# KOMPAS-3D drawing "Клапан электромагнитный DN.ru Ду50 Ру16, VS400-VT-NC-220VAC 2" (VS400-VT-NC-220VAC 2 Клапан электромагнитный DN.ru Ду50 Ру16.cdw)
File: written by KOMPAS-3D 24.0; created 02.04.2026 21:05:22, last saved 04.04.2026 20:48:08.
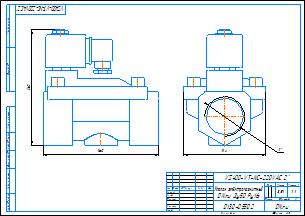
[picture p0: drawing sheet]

Document properties: c3d_UniqueCompID: ef56311e-7521-43dc-8291-0e6108b3d81d; Обозначение: VS400-ET-NC-220VAC 2; Наименование: Клапан электромагнитный DN.ru Ду50 Ру16; Автор: artio; Класс точности: c; Знак неуказанной шероховатости: Шероховатость не задана; Рассекать на разрезах: Да; c3d_UniqueCompID: ef56311e-7521-43dc-8291-0e6108b3d81d; Обозначение: VS400-ET-NC-220VAC 1; Наименование: Клапан электромагнитный DN.ru Ду25 Ру16; Автор: artio; Класс точности: c; Знак неуказанной шероховатости: Шероховатость не задана; Рассекать на разрезах: Да; c3d_UniqueCompID: ef56311e-7521-43dc-8291-0e6108b3d81d; Обозначение: VS400-ET-NC-220VAC 1-2; Наименование: Клапан электромагнитный DN.ru Ду15 Ру16; Автор: artio; Класс точности: c; Знак неуказанной шероховатости: Шероховатость не задана; Рассекать на разрезах: Да; c3d_UniqueCompID: ef56311e-7521-43dc-8291-0e6108b3d81d; Обозначение: VS400-ET-NC-220VAC 3-4; Наименование: Клапан электромагнитный DN.ru Ду20 Ру16; Автор: artio; Класс точности: c; Знак неуказанной шероховатости: Шероховатость не задана; Рассекать на разрезах: Да; c3d_UniqueCompID: ef56311e-7521-43dc-8291-0e6108b3d81d; Обозначение: VS400-ET-NC-220VAC 1 1-4; Наименование: Клапан электромагнитный DN.ru Ду32 Ру16; Автор: artio; Класс точности: c; Знак неуказанной шероховатости: Шероховатость не задана; Рассекать на разрезах: Да; c3d_UniqueCompID: ef56311e-7521-43dc-8291-0e6108b3d81d; Обозначение: VS400-ET-NC-220VAC 3-8; Наименование: Клапан электромагнитный DN.ru Ду10 Ру16; Автор: artio; Класс точности: c; Знак неуказанной шероховатости: Шероховатость не задана; Рассекать на разрезах: Да; c3d_UniqueCompID: ef56311e-7521-43dc-8291-0e6108b3d81d; Обозначение: VS400-ET-NC-220VAC 1 1-2; Наименование: Клапан электромагнитный DN.ru Ду40 Ру16; Автор: artio; Класс точности: c; Знак неуказанной шероховатости: Шероховатость не задана; Рассекать на разрезах: Да; Автор: artio; Форматы листов документа: A3; Полное имя файла: VS400-VT-NC-220VAC 2 Клапан электромагнитный DN.ru Ду50 Ру16.m3d; Масса: 3.509; Наименование: Клапан электромагнитный DN.ru Ду50 Ру16; Количество листов документа: 1; Примечание: D130-04703

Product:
- Body: Тело 1  | qty 1
    Масса: 7.119215
- Part/product: Клапан электромагнитный DN.ru Ду50 Ру16  | designation VS400-VT-NC-220VAC 2
    Масса: 3.509
    Раздел спецификации: Прочие изделия
    Примечание: D130-04703
    additional columns: ef56311e-7521-43dc-8291-0e6108b3d81d; VS400-ET-NC-220VAC 2; artio; c; Шероховатость не задана; Да

Views: Вид 1, Спереди
Referenced files in C:\Users\artio\OneDrive\Рабочий стол\Клапан электромагнитный DN.ru VS4x-xT-NC-x\DN10\: VS400-ET-NC-220VAC 3-8 Клапан электромагнитный DN.ru Ду10 Ру16.m3d, VS400-ET-NC-220VAC 3-8 Клапан электромагнитный DN.ru Ду10 Ру16.cdw
Referenced files in C:\Users\artio\OneDrive\Рабочий стол\Клапан электромагнитный DN.ru\VS400-VT-NC\VS400-VT-NC-220VAC\: VS400-VT-NC-220VAC 2 Клапан электромагнитный DN.ru Ду50 Ру16.m3d
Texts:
  VS400-VT-NC-220VAC 2
  Клапан электромагнитный
  DN.ru Ду50 Ру16
  VS400-VT-NC-220VAC 2"
  VS400-VT-NC-220VAC 2"-
  Клапан электромагнитный DN.ru Ду50 Ру16
  VS400-VT-NC-220VAC 2 Клапан электромагнитный DN.ru Ду50 Ру16
Dimensions and other numbers on the sheet: 0; 3; 2; 4; 114; 1:1; 1; 3,51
